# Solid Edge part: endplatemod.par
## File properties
Author: Deepak Maini
Template: NORMENG.PAR
Last saved by: MYPC
Revision: 2
Application: Solid Edge
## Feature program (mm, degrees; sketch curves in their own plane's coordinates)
sketch for "unnamed Protrusion 1" plane through (0, 0, 0) normal (0, 0, 1) x-axis (1, 0, 0)
  line (-50.8, 46.0858) -> (-50.8, -55.5142)
  line (-50.8, -55.5142) -> (50.8, -55.5142)
  line (50.8, -55.5142) -> (50.8, 46.0858)
  line (50.8, 46.0858) -> (-50.8, 46.0858)
extrude "unnamed Protrusion 1" add finite 12.7 along +normal
sketch for "unnamed Hole 1" plane through (0, -4.7142, 12.7) normal (0, 0, 1) x-axis (1, 0, 0)
  hole centre (-38.1, -38.1) bore radius 3.175
hole "unnamed Hole 1" through
sketch for "unnamed Hole 2" plane through (0, -4.7142, 12.7) normal (0, 0, 1) x-axis (1, 0, 0)
  hole centre (38.1, -38.1) bore radius 3.175
hole "unnamed Hole 2" through
sketch for "unnamed Hole 3" plane through (0, -4.7142, 12.7) normal (0, 0, 1) x-axis (1, 0, 0)
  hole centre (38.1, 38.1) bore radius 3.175
hole "unnamed Hole 3" through
sketch for "unnamed Hole 4" plane through (0, -4.7142, 12.7) normal (0, 0, 1) x-axis (1, 0, 0)
  hole centre (-38.1, 38.1) bore radius 3.175
  dimension (linear) = 38.1
hole "unnamed Hole 4" through
pattern "unnamed Pattern 1" of "unnamed Hole 1", "unnamed Hole 2", "unnamed Hole 3", "unnamed Hole 4"
sketch for "unnamed Hole 5" plane through (0, -4.7142, 12.7) normal (0, 0, 1) x-axis (1, 0, 0)
  hole centre (0, 0) bore radius 12.7
hole "unnamed Hole 5" through
sketch for "unnamed Hole 6" plane through (0, -4.7142, 12.7) normal (0, 0, 1) x-axis (1, 0, 0)
  hole centre (-20.6375, 0) bore radius 2.3812
  dimension (linear) = 20.6375
hole "unnamed Hole 6" through
pattern "unnamed Pattern 2" of "unnamed Hole 6"
pattern "unnamed Pattern 3"
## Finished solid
Body 1: solid body, 15 faces, 30 edges, 8 vertices.
  Faces by surface: cylinder 9, plane 6
  Edges by curve: circle 18, line 12
Bounding box of the edges (mm): 101.600 x 101.600 x 12.700, from (-50.8, -55.5142, 0) to (50.8, 46.0858, 12.7).
Cylindrical faces by radius (mm): R2.3812 x4, R3.175 x4, R12.7 x1
Planar faces by outward normal: +x 1, +y 1, +z 1, -x 1, -y 1, -z 1
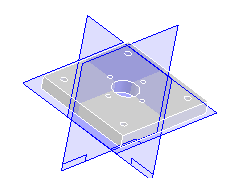
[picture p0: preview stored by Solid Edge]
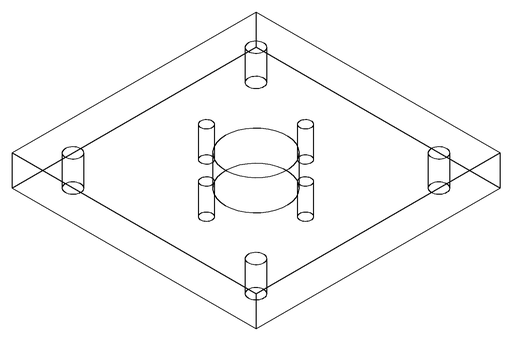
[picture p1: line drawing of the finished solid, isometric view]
